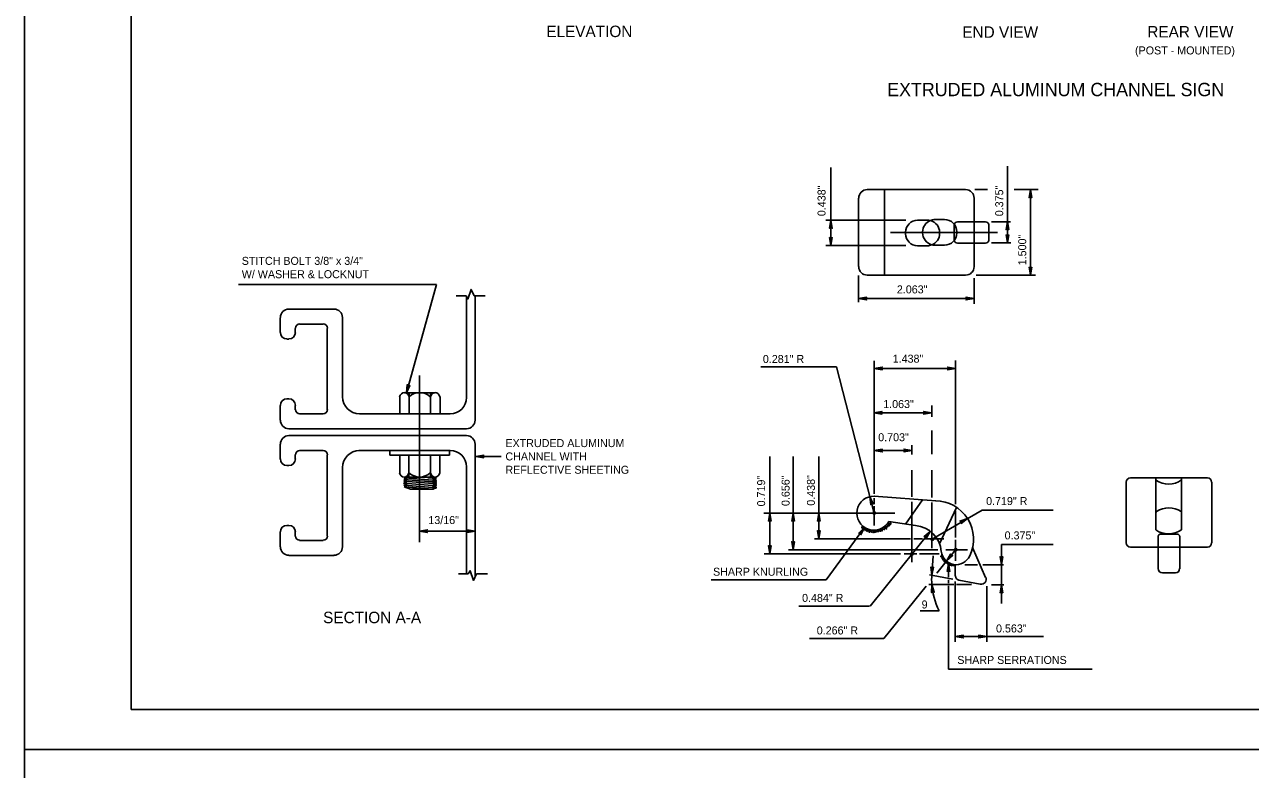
# Model space of a CAD drawing. Extents: x 647822 to 649292, y 298458 to 299646.
# Drawn here: x 647822.3 to 648281.8, y 299044.1 to 299323.4 of the extents above; entities that cross this region are included whole.
import ezdxf

# ---------------------------------------------------------------- set-up
doc = ezdxf.new("R2010")
doc.units = 0
for name, color, linetype in [('1', 7, 'Continuous'), ('2', 7, 'Continuous'), ('3', 7, 'Continuous'), ('XCS-GRID-MIN', 7, 'Continuous')]:
    doc.layers.add(name, color=color, linetype=linetype)

# ---------------------------------------------------------------- blocks, each defined once
blk = doc.blocks.new('RARROW')
at = {"layer": '3'}
blk.add_lwpolyline([(-2.2695, 0.285), (-2.184875, 0.12075), (0, 0), (-2.2695, 0.285), (-2.38575, 0.384625), (0, 0), (-2.183125, -0.108), (-2.262875, -0.2705), (0, 0), (-2.38575, -0.379125), (-2.262875, -0.2705)], dxfattribs=at)

msp = doc.modelspace()

# ---------------------------------------------------------------- linework, layer by layer
at = {"layer": '1'}
for p, q in [((647862.31, 299630.63), (647862.31, 299066.63)), ((648648.31, 299066.63), (647862.31, 299066.63)), ((647862.31, 299066.63), (648448.31, 299066.63))]:
    msp.add_line(p, q, dxfattribs=at)
at = {"layer": '2'}
for p, q in [((648124.58, 299269.83), (648124.58, 299250.07)), ((648190.69, 299270.28), (648190.69, 299249.57)), ((648134.94, 299258.32), (648134.94, 299232.7)), ((648138.19, 299261.57), (648175.06, 299261.57)), ((648144.69, 299261.57), (648144.69, 299229.45)), ((648178.31, 299258.32), (648178.31, 299232.57)), ((648178.44, 299261.57), (648183.28, 299261.57)), ((648193.22, 299261.57), (648202.19, 299261.57)), ((648199.31, 299261.57), (648199.31, 299229.45)), ((648122.7, 299250.07), (648152.6, 299250.07)), ((648124.58, 299250.07), (648124.58, 299240.57)), ((648160.69, 299250.07), (648157.06, 299250.07)), ((648163.25, 299250.31), (648167.12, 299250.31)), ((648178.31, 299249.45), (648172.06, 299249.45)), ((648178.31, 299249.45), (648182.46, 299249.45)), ((648184.69, 299249.45), (648191.81, 299249.45)), ((648190.69, 299249.57), (648190.69, 299241.57)), ((648146.94, 299245.45), (648187.02, 299245.45)), ((648152.56, 299245.57), (648152.56, 299244.95)), ((648158.94, 299245.32), (648158.94, 299245.7)), ((648165.31, 299245.07), (648165.31, 299245.45)), ((648170.71, 299248.1), (648170.71, 299242.8)), ((648171.74, 299245.69), (648171.74, 299245.31)), ((648183.81, 299248.1), (648183.81, 299242.8)), ((648122.7, 299240.57), (648152.6, 299240.57)), ((648124.58, 299240.7), (648124.58, 299240.57)), ((648157.06, 299240.45), (648160.69, 299240.45)), ((648163.06, 299240.7), (648167.06, 299240.7)), ((648172.06, 299241.45), (648178.31, 299241.45)), ((648178.31, 299241.45), (648182.46, 299241.45)), ((648184.69, 299241.57), (648191.94, 299241.57)), ((648190.69, 299241.7), (648190.69, 299241.57)), ((647902.47, 299226), (647976.69, 299226)), ((647965.44, 299185.38), (647976.69, 299226)), ((648134.94, 299229.32), (648134.94, 299219.32)), ((648138.19, 299229.45), (648175.06, 299229.45)), ((648178.19, 299228.32), (648178.19, 299218.7)), ((648178.94, 299229.45), (648201.19, 299229.45)), ((647984.06, 299221.75), (647987.81, 299221.75)), ((647987.94, 299221.75), (647987.94, 299183.63)), ((647990.81, 299221.75), (647994.94, 299221.75)), ((647991.19, 299221.75), (647991.19, 299175.13)), ((648134.94, 299220.7), (648178.19, 299220.7)), ((647918.19, 299208), (647918.19, 299213.5)), ((647921.44, 299216.75), (647938.31, 299216.75)), ((647941.44, 299213.5), (647941.44, 299183.88)), ((647923.81, 299208), (647923.81, 299209.5)), ((647925.44, 299211.13), (647934.31, 299211.13)), ((647935.81, 299209.5), (647935.81, 299179)), ((647920.69, 299205.5), (647921.44, 299205.5)), ((648098.26, 299195.06), (648126.67, 299195.06)), ((648140.81, 299140.13), (648126.67, 299195.06)), ((648140.81, 299147.5), (648140.81, 299197.38)), ((648140.81, 299194.48), (648171.31, 299194.48)), ((648171.31, 299143.63), (648171.31, 299197.5)), ((647970.31, 299129.38), (647970.31, 299191.88)), ((647964.69, 299185.38), (647976.19, 299185.38)), ((647965.44, 299185.38), (647965.44, 299185.38)), ((647966.44, 299177.5), (647966.44, 299185.38)), ((647974.44, 299185.38), (647974.44, 299177.38)), ((647918.19, 299175.13), (647918.19, 299180.63)), ((647921.44, 299183.13), (647920.69, 299183.13)), ((647923.81, 299179), (647923.81, 299180.63)), ((647962.94, 299177.38), (647962.94, 299183.88)), ((647978.06, 299183.88), (647978.06, 299177.38)), ((648162.44, 299176.4), (648162.44, 299180.6)), ((647934.31, 299177.5), (647925.44, 299177.5)), ((647981.81, 299177.5), (647947.94, 299177.5)), ((648140.69, 299177.85), (648162.31, 299177.85)), ((647987.94, 299171.88), (647921.44, 299171.88)), ((648162.44, 299162.4), (648162.44, 299171.27)), ((647987.94, 299169.38), (647921.44, 299169.38)), ((647991.19, 299116.38), (647991.19, 299166.25)), ((647918.19, 299166.13), (647918.19, 299160.5)), ((647923.81, 299162.13), (647923.81, 299160.5)), ((647934.31, 299163.75), (647925.44, 299163.75)), ((647935.81, 299131.63), (647935.81, 299162.13)), ((647981.81, 299163.75), (647947.56, 299163.75)), ((647959.19, 299163.63), (647959.19, 299162)), ((647959.19, 299162), (647981.56, 299162)), ((647962.94, 299161.75), (647962.94, 299155.25)), ((647966.31, 299162), (647966.31, 299153.75)), ((647974.44, 299153.75), (647974.44, 299161.75)), ((647977.94, 299155.25), (647977.94, 299161.75)), ((647981.56, 299162), (647981.56, 299163.63)), ((648140.81, 299163.72), (648154.94, 299163.72)), ((648154.94, 299162.25), (648154.94, 299165.67)), ((647921.44, 299158.13), (647920.69, 299158.13)), ((647941.44, 299127.63), (647941.44, 299157.25)), ((647987.94, 299117.5), (647987.94, 299157.63)), ((647991.44, 299161.5), (648000.94, 299161.5)), ((647991.44, 299161.5), (647991.44, 299161.5)), ((648101.63, 299161.53), (648101.63, 299125)), ((648110.4, 299126.5), (648110.4, 299161.53)), ((648120, 299130.63), (648120, 299161.53)), ((647965.69, 299153.25), (647964.44, 299152.88)), ((647964.44, 299152.88), (647965.56, 299152.5)), ((647965.56, 299152.5), (647964.44, 299152.25)), ((647964.56, 299153.5), (647965.69, 299153.25)), ((647976.69, 299151.88), (647964.56, 299152.88)), ((647964.69, 299153.75), (647976.06, 299153.75)), ((647976.69, 299152.5), (647964.81, 299153.5)), ((647976.69, 299153.25), (647973.44, 299153.5)), ((648154.94, 299146.38), (648154.94, 299156.34)), ((648162.44, 299146.13), (648162.44, 299156.34)), ((648265.69, 299153.5), (648236.81, 299153.5)), ((648246.31, 299153.38), (648246.31, 299133.94)), ((648255.94, 299153.38), (648255.94, 299133.99)), ((647965.56, 299151.75), (647964.31, 299151.5)), ((647964.31, 299151.5), (647965.69, 299151.13)), ((647964.44, 299152.25), (647965.56, 299151.75)), ((647976.56, 299150.5), (647964.44, 299151.5)), ((647965.69, 299151.13), (647964.44, 299150.75)), ((647964.44, 299150.75), (647965.56, 299150.38)), ((647976.69, 299151.25), (647964.56, 299152.25)), ((647976.69, 299149.75), (647964.56, 299150.75)), ((647965.56, 299150.38), (647964.56, 299150.13)), ((647964.56, 299150.13), (647966.94, 299149.25)), ((647975.19, 299149.25), (647964.69, 299150.13)), ((647975.56, 299149.25), (647966.94, 299149.25)), ((648235.19, 299151.88), (648235.19, 299129.13)), ((648267.31, 299151.88), (648267.31, 299129.13)), ((648140.81, 299146.63), (648163.94, 299144.88)), ((648140.81, 299143.63), (648140.81, 299145.88)), ((648152.56, 299136.13), (648158.94, 299145.25)), ((648154.94, 299121.88), (648154.94, 299144.5)), ((648162.44, 299127.13), (648162.44, 299144.25)), ((648099.38, 299140.25), (648148.56, 299140.25)), ((648140.81, 299135.63), (648140.81, 299142.88)), ((648162.31, 299130.38), (648181.19, 299141.38)), ((648165.31, 299128.75), (648171.69, 299142.38)), ((648171.31, 299131.13), (648171.31, 299141.13)), ((648181.19, 299141.38), (648207.92, 299141.38)), ((647920.69, 299135.63), (647921.44, 299135.63)), ((648122.72, 299115.26), (648137.19, 299134.88)), ((648156.31, 299135.63), (648146.31, 299137.13)), ((647918.19, 299133.25), (647918.19, 299127.63)), ((647923.81, 299133.25), (647923.81, 299131.63)), ((647925.44, 299130), (647934.31, 299130)), ((647970.31, 299133.5), (647991.19, 299133.5)), ((648118.41, 299130.63), (648154.44, 299130.63)), ((648139.23, 299105.38), (648161.81, 299133.38)), ((648155.69, 299130.63), (648158.94, 299130.63)), ((648159.81, 299130.63), (648166.94, 299130.63)), ((648162.44, 299130.63), (648162.44, 299130.63)), ((648171.31, 299122.38), (648171.31, 299130.25)), ((648247.19, 299119.38), (648247.19, 299131.63)), ((648248.06, 299132.38), (648254.44, 299132.38)), ((648255.31, 299131.63), (648255.31, 299119.38)), ((648099.53, 299125), (648150.69, 299125)), ((648108.67, 299126.5), (648164.69, 299126.5)), ((648152.06, 299125), (648156.81, 299125)), ((648154.94, 299125), (648154.94, 299125)), ((648154.94, 299125), (648154.94, 299125)), ((648157.81, 299125), (648165.19, 299125)), ((648164.23, 299117.72), (648171.31, 299126.5)), ((648167.69, 299126.5), (648175.81, 299126.5)), ((648171.31, 299126.5), (648171.31, 299126.5)), ((648182.56, 299116.13), (648177.69, 299127.38)), ((648188.44, 299120.88), (648188.44, 299128.5)), ((648188.44, 299128.5), (648207.92, 299128.5)), ((648265.69, 299127.5), (648236.81, 299127.5)), ((647921.44, 299124.38), (647938.31, 299124.38)), ((648162.36, 299116.98), (648162.94, 299124.25)), ((648168.69, 299116.25), (648168.69, 299121.38)), ((648171.19, 299120.88), (648171.19, 299116.63)), ((648174.81, 299120.88), (648179.44, 299120.88)), ((648181.44, 299120.88), (648189.19, 299120.88)), ((648188.44, 299113.25), (648188.44, 299120.88)), ((647984.94, 299117.5), (647988.56, 299117.5)), ((647991.69, 299117.5), (647995.81, 299117.5)), ((648161.56, 299117.13), (648170.31, 299115.5)), ((648248.81, 299117.88), (648253.69, 299117.88)), ((648079.62, 299115.26), (648122.72, 299115.26)), ((648144.43, 299093.18), (648160.26, 299112.8)), ((648161.31, 299113.5), (648170.69, 299113.5)), ((648168.69, 299114), (648168.69, 299115.25)), ((648168.69, 299081.7), (648168.69, 299113)), ((648171.19, 299091.98), (648171.19, 299114.63)), ((648171.69, 299113.5), (648177.31, 299113.5)), ((648172.56, 299115.13), (648180.56, 299113.63)), ((648182.94, 299091.98), (648182.94, 299112.88)), ((648184.69, 299113.38), (648189.31, 299113.38)), ((648188.44, 299106.38), (648188.44, 299113.5)), ((648112.51, 299105.38), (648138.98, 299105.38)), ((648157.97, 299103.56), (648165.1, 299103.56)), ((648116.58, 299093.18), (648144.43, 299093.18)), ((648171.19, 299093.98), (648204.3, 299093.98)), ((648168.69, 299081.7), (648222.48, 299081.7))]:
    msp.add_line(p, q, dxfattribs=at)
for points in [[(647987.81, 299221.75), (647988.44, 299220.5), (647989.69, 299224.13), (647990.81, 299221.75)], [(647975.94, 299153.5), (647976.56, 299153.25), (647975.56, 299152.88), (647976.69, 299152.5), (647975.56, 299152.25), (647976.69, 299151.88), (647975.56, 299151.5), (647976.69, 299151.13), (647975.56, 299150.75), (647976.69, 299150.5), (647975.44, 299150.13), (647976.69, 299149.75), (647975.19, 299149.25)], [(647988.56, 299117.5), (647989.31, 299118.63), (647990.56, 299115), (647991.69, 299117.5)]]:
    msp.add_lwpolyline(points, dxfattribs=at)
for centre in [(648140.78, 299140.23), (648162.53, 299130.44), (648154.89, 299124.97), (648171.35, 299126.49)]:
    msp.add_circle(centre, 0.443, dxfattribs=at)
for centre, radius, start, end in [((648138.18, 299258.32), 3.2, 90, 180), ((648175.05, 299258.32), 3.2, 0, 90), ((648157.06, 299245.57), 4.5, 90, 180), ((648163.56, 299245.69), 4.62, 112.9887, 180), ((648160.83, 299245.48), 4.59, 77.9667, 91.7716), ((648163.56, 299245.69), 4.62, 90, 112.8645), ((648160.68, 299245.49), 4.62, 0, 75.8124), ((648167.12, 299245.69), 4.62, 0, 90), ((648172.06, 299248.1), 1.35, 90, 180), ((648182.46, 299248.1), 1.35, 0, 90), ((648157.06, 299244.95), 4.5, 180, 270), ((648163.56, 299245.31), 4.62, 180, 253.8798), ((648160.68, 299245.1), 4.62, 290.5941, 0), ((648167.12, 299245.31), 4.62, 270, 0), ((648160.48, 299245.54), 5.1, 272.3653, 291.0122), ((648163.56, 299245.31), 4.62, 254.1406, 270), ((648172.06, 299242.8), 1.35, 180, 270), ((648182.46, 299242.8), 1.35, 270, 0), ((648138.18, 299232.66), 3.2, 180, 270), ((648175.05, 299232.66), 3.2, 270, 0), ((647921.4, 299213.57), 3.2, 90, 180), ((647938.29, 299213.57), 3.2, 0, 90), ((647920.66, 299208), 2.46, 180, 270), ((647921.4, 299208), 2.46, 270, 0), ((647925.47, 299209.55), 1.6, 90, 180), ((647934.27, 299209.55), 1.6, 0, 90), ((647920.66, 299180.65), 2.46, 90, 180), ((647921.4, 299180.65), 2.46, 0, 90), ((647947.89, 299183.87), 6.4, 180, 270), ((647981.81, 299183.63), 6.16, 270, 0), ((647925.47, 299179.07), 1.6, 180, 270), ((647934.27, 299179.07), 1.6, 270, 0), ((647921.4, 299175.08), 3.2, 180, 270), ((647988, 299175.08), 3.2, 270, 0), ((647921.4, 299166.11), 3.2, 90, 180), ((647988, 299166.11), 3.2, 0, 90), ((647925.47, 299162.12), 1.6, 90, 180), ((647934.27, 299162.12), 1.6, 0, 90), ((647947.89, 299157.32), 6.4, 90, 180), ((647981.81, 299157.57), 6.16, 0, 90), ((647920.66, 299160.54), 2.46, 180, 270), ((647921.4, 299160.54), 2.46, 270, 0), ((648236.8, 299151.84), 1.6, 90, 180), ((648251.14, 299159.57), 8.44, 235.4439, 305.1656), ((648265.66, 299151.84), 1.6, 0, 90), ((648140.68, 299140.21), 6.4, 88.6252, 330.6548), ((648163.58, 299130.46), 14.44, 334.348, 89.3872), ((648246.83, 299140.51), 0.4, 123.07, 180), ((648251.22, 299133.77), 8.44, 56.7397, 123.07), ((647920.66, 299133.2), 2.46, 90, 180), ((647921.4, 299133.2), 2.46, 0, 90), ((648155.5, 299125.15), 10.43, 4.0856, 85.4934), ((647925.47, 299131.65), 1.6, 180, 270), ((647934.27, 299131.65), 1.6, 270, 0), ((648251.09, 299140.9), 8.44, 235.5078, 305.0689), ((648248.03, 299131.59), 0.8, 90, 180), ((648254.46, 299131.59), 0.8, 0, 90), ((647921.4, 299127.63), 3.2, 180, 270), ((647938.29, 299127.63), 3.2, 270, 0), ((648171.48, 299126.51), 5.6, 185.7365, 335.7963), ((648236.8, 299129.14), 1.6, 180, 270), ((648265.66, 299129.14), 1.6, 270, 0), ((648187.85, 299115.48), 25.53, 176.3698, 184.437), ((648172.83, 299116.67), 1.6, 180, 259.2899), ((648180.94, 299115.42), 1.85, 259.5085, 24.0163), ((648248.83, 299119.42), 1.6, 180, 270), ((648253.66, 299119.42), 1.6, 270, 0), ((648191.91, 299116.21), 29.64, 184.2804, 205.2635)]:
    msp.add_arc(centre, radius, start, end, dxfattribs=at)
for centre, major_axis, ratio, start_param, end_param in [((647964.69, 299183.34), (0, 2.07), 0.888639, 4.973303, 7.593068), ((647970.43, 299178.2), (0, 7.22), 0.88864, 5.618065, 6.948305), ((647976.24, 299183.41), (0, 2.01), 0.888639, 4.948347, 7.618023), ((647964.63, 299155.85), (0, -2.07), 0.88864, 4.973303, 7.593068), ((647970.38, 299161), (0, -7.22), 0.88864, 5.618065, 6.948305), ((647976.19, 299155.79), (0, -2.01), 0.888639, 4.948347, 7.618023)]:
    msp.add_ellipse(centre, major_axis=major_axis, ratio=ratio, start_param=start_param, end_param=end_param, dxfattribs=at)
for points in [[(648136.31, 299135.38), (648136.19, 299134.63), (648136.94, 299135), (648136.81, 299134.13), (648137.44, 299134.38), (648137.31, 299133.75), (648138.06, 299134.13), (648138.06, 299133.38), (648138.69, 299133.75), (648138.94, 299133), (648139.44, 299133.75), (648139.94, 299133), (648140.31, 299133.38), (648140.56, 299132.88), (648140.94, 299133.63), (648141.31, 299133), (648141.69, 299133.88), (648142.06, 299133.13)], [(648141.94, 299133.88), (648142.31, 299133.25), (648142.69, 299134), (648143.06, 299133.38), (648143.44, 299134.13), (648143.69, 299133.5), (648144.06, 299134.38), (648144.56, 299134), (648144.69, 299134.75), (648145.44, 299134.25), (648145.19, 299135.13), (648145.94, 299135.13), (648145.94, 299135.75), (648146.56, 299135.5), (648146.19, 299136.25), (648147.06, 299136.13), (648146.56, 299137), (648147.19, 299136.88)], [(648166.19, 299124.63), (648165.81, 299123.88), (648166.56, 299123.88), (648166.19, 299123.25), (648166.94, 299123.25), (648166.44, 299122.75), (648167.31, 299122.75), (648166.94, 299122.13), (648167.81, 299122.25), (648167.69, 299121.5), (648168.44, 299121.75), (648168.44, 299121), (648169.06, 299121.38), (648169.06, 299120.63), (648169.81, 299121.13), (648169.81, 299120.5), (648170.56, 299121), (648170.56, 299120.38)]]:
    msp.add_spline(points, degree=3, dxfattribs=at)
at = {"layer": 'XCS-GRID-MIN'}
for points in [[(647822.31, 299645.63), (648663.31, 299645.63), (648663.31, 299051.63), (647822.31, 299051.63)], [(647822.31, 299051.63), (648663.31, 299051.63), (648663.31, 298457.63), (647822.31, 298457.63)]]:
    msp.add_lwpolyline(points, close=True, dxfattribs=at)

# ---------------------------------------------------------------- block references
at = {"layer": '2'}
for p, xscale, yscale, rotation in [((648199.31, 299261.57), 1.2574347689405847, 1.3092961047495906, 89.99999999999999), ((648124.58, 299250.07), 1.2574347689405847, 1.3092961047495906, 89.99999999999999), ((648190.69, 299249.57), 1.2574347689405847, 1.3092961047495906, 89.99999999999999), ((648190.69, 299241.57), 1.2574347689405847, 1.3092961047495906, -90.00000000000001), ((648124.58, 299240.57), 1.2574347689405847, 1.3092961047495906, -90.00000000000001), ((648199.31, 299229.45), 1.2574347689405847, 1.3092961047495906, -90.00000000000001), ((648134.94, 299220.7), 1.2574347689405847, 1.3092961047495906, 180), ((648140.81, 299194.48), 1.2574347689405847, 1.3092961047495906, 180), ((647965.44, 299185.38), 1.257434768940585, 1.3092961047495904, -105.47863816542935), ((648140.69, 299177.85), 1.2574347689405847, 1.3092961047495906, 180), ((647991.44, 299161.5), 1.2574347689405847, 1.3092961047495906, 180), ((648140.81, 299163.72), 1.2574347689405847, 1.3092961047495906, 180), ((648139.19, 299146.43), 1.2574347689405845, 1.3092961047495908, 104.99324708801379), ((648101.63, 299140.25), 1.2574347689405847, 1.3092961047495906, 89.99999999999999), ((648110.4, 299140.25), 1.2574347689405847, 1.3092961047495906, 89.99999999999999), ((648120, 299140.25), 1.2574347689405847, 1.3092961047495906, 89.99999999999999), ((648175.81, 299138.25), 1.257434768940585, 1.3092961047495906, 28.994801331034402), ((648137.19, 299134.88), 1.2574347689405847, 1.3092961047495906, 54.05716951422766), ((647970.31, 299133.5), 1.2574347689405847, 1.3092961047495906, 180), ((648110.4, 299126.5), 1.2574347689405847, 1.3092961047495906, -90.00000000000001), ((648120, 299130.63), 1.2574347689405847, 1.3092961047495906, -90.00000000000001), ((648161.81, 299133.38), 1.2574347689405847, 1.3092961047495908, 49.686306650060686), ((648101.63, 299125), 1.2574347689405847, 1.3092961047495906, -90.00000000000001), ((648167.87, 299122.23), 1.257434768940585, 1.3092961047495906, -128.70988085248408), ((648168.69, 299121.38), 1.2574347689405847, 1.3092961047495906, 89.99999999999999), ((648188.44, 299120.88), 1.2574347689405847, 1.3092961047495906, -90.00000000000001), ((648162.37, 299116.97), 1.257434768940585, 1.3092961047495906, -93.60514013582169), ((648162.39, 299113.5), 1.2574347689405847, 1.3092961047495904, 97.67734975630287), ((648188.44, 299113.38), 1.2574347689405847, 1.3092961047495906, 89.99999999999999), ((648171.19, 299093.98), 1.2574347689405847, 1.3092961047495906, 180)]:
    msp.add_blockref('RARROW', p, dxfattribs=dict(at, xscale=xscale, yscale=yscale, rotation=rotation))
at = {"layer": '2', "xscale": 1.2574347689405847, "yscale": 1.3092961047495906}
for p in [(648178.19, 299220.7), (648171.31, 299194.48), (648162.31, 299177.85), (648154.94, 299163.72), (647991.19, 299133.5), (648182.94, 299093.98)]:
    msp.add_blockref('RARROW', p, dxfattribs=at)

# ---------------------------------------------------------------- texts
at = {"layer": '2'}
for s, height, p in [('ELEVATION', 4.3, (648017.87, 299318.71)), ('END VIEW', 4.3, (648173.8, 299318.44)), ('REAR VIEW', 4.3, (648243.15, 299318.57)), ('(POST - MOUNTED)', 3, (648238.55, 299312.22)), ('EXTRUDED ALUMINUM CHANNEL SIGN', 5, (648145.65, 299296.56)), ('STITCH BOLT 3/8" x 3/4"', 3, (647903.73, 299233.32)), ('W/ WASHER & LOCKNUT', 3, (647903.73, 299228.32)), ('2.063"', 3, (648149.28, 299222.62)), ('0.281" R', 3, (648099.06, 299196.53)), ('1.438"', 3, (648147.72, 299196.65)), ('1.063"', 3, (648144.16, 299179.63)), ('EXTRUDED ALUMINUM', 3, (648002.56, 299165)), ('0.703"', 3, (648142.29, 299167.2)), ('CHANNEL WITH', 3, (648002.56, 299160)), ('REFLECTIVE SHEETING', 3, (648002.56, 299155)), ('0.719" R', 3, (648182.73, 299143.26)), ('13/16"', 3, (647973.67, 299136.14)), ('0.375"', 3, (648189.67, 299130.39)), ('SHARP KNURLING', 3, (648080.37, 299116.77)), ('0.484" R', 3, (648113.75, 299106.95)), ('9', 3, (648158.56, 299104.49)), ('SECTION A-A', 4.3, (647934.23, 299098.97)), ('0.266" R', 3, (648119.25, 299094.76)), ('0.563"', 3, (648186.45, 299095.51)), ('SHARP SERRATIONS', 3, (648171.93, 299083.7))]:
    msp.add_text(s, height=height, dxfattribs=at).set_placement(p)
for s, p in [(' 0.438"', (648122.54, 299250.47)), (' 0.375"', (648189.14, 299250.44)), (' 1.500"', (648197.77, 299232.05)), ('0.719"', (648099.9, 299142.77)), ('0.656"', (648109.08, 299142.9)), ('0.438"', (648118.57, 299143.02))]:
    msp.add_text(s, height=3, rotation=90, dxfattribs=at).set_placement(p)

doc.saveas('drawing.dxf')
